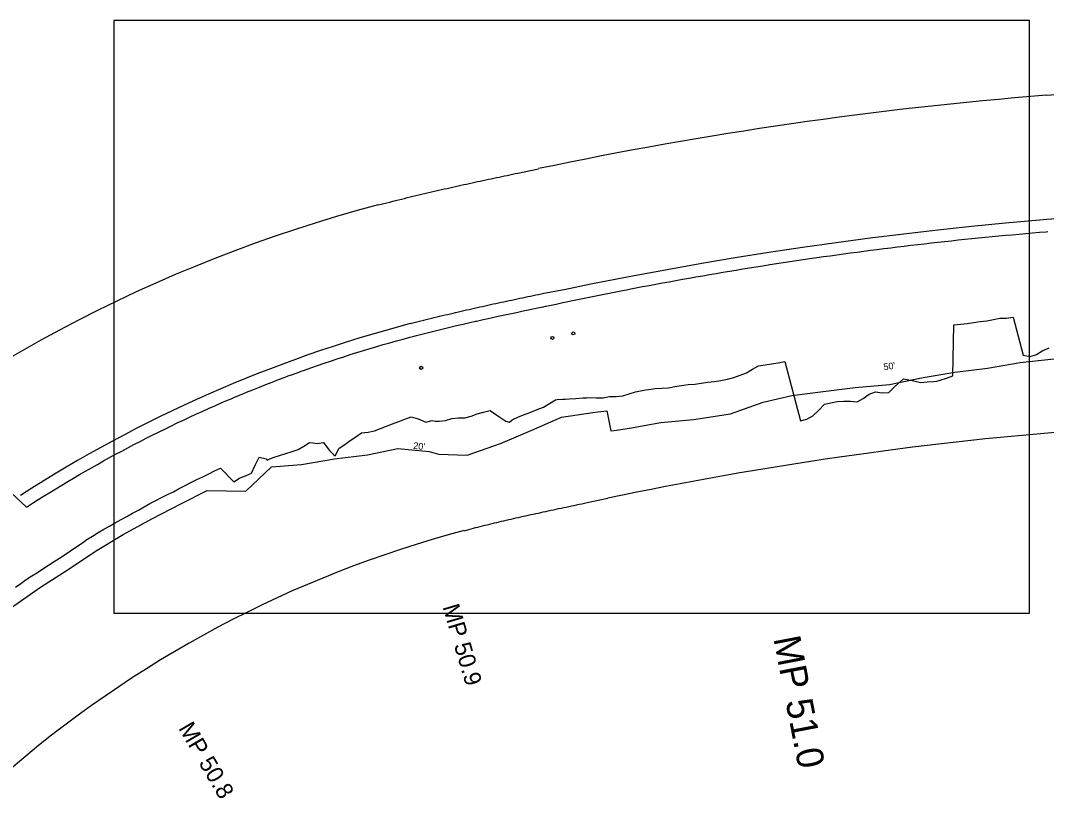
# Model space of a CAD drawing. Extents: x 7860037 to 7875910, y 598622 to 603049.
# Drawn here: x 7868936 to 7870460, y 601894 to 603049 of the extents above; entities that cross this region are included whole.
import ezdxf

# ---------------------------------------------------------------- set-up
doc = ezdxf.new("R2010")
doc.units = 0
for name, color, linetype in [('Level 11', 7, 'Continuous'), ('Level 15', 7, 'Continuous'), ('Level 16', 7, 'Continuous'), ('Level 24', 7, 'Continuous'), ('Level 63', 7, 'Continuous'), ('P_RW_EASE_Perm', 7, 'Continuous')]:
    doc.layers.add(name, color=color, linetype=linetype)

msp = doc.modelspace()

# ---------------------------------------------------------------- linework, layer by layer
at = {"layer": 'Level 11'}
for centre in [(7869757.2, 602584.3), (7869726.2, 602577.8), (7869531.3, 602533.3)]:
    msp.add_circle(centre, 2.25, dxfattribs=at)
at = {"layer": 'Level 16'}
for points in [[(7868915.1, 602354.4), (7868945.4, 602326.6), (7868954.1, 602332.1), (7868962.7, 602337.6), (7868971.4, 602343), (7868980.1, 602348.4), (7868988.8, 602353.8), (7868997.6, 602359.1), (7869006.4, 602364.4), (7869015.2, 602369.6), (7869024, 602374.8), (7869032.9, 602379.9), (7869041.8, 602385), (7869050.7, 602390), (7869059.7, 602395), (7869068.6, 602400), (7869077.6, 602404.9), (7869086.7, 602409.7), (7869095.7, 602414.5), (7869104.8, 602419.3), (7869113.9, 602424), (7869123, 602428.7), (7869132.1, 602433.3), (7869141.3, 602437.9), (7869150.5, 602442.4), (7869159.7, 602446.9), (7869168.9, 602451.4), (7869178.2, 602455.7), (7869187.5, 602460.1), (7869196.8, 602464.4), (7869206.1, 602468.6), (7869215.5, 602472.8), (7869216.6, 602473.3), (7869224.8, 602477), (7869234.2, 602481.1), (7869243.6, 602485.1), (7869249.3, 602487.5), (7869252.3, 602488.8), (7869253.1, 602489.1), (7869261.6, 602492.7), (7869262.5, 602493.1), (7869265.6, 602494.3), (7869272, 602497), (7869281.5, 602500.8), (7869291, 602504.7), (7869300.5, 602508.4), (7869310.1, 602512.1), (7869319.6, 602515.8), (7869329.2, 602519.4), (7869334, 602521.2), (7869338.8, 602523), (7869348.5, 602526.5), (7869351.1, 602527.5), (7869352.9, 602528.1), (7869356.6, 602529.4), (7869358.1, 602530), (7869367.7, 602533.4), (7869377.4, 602536.8), (7869387.1, 602540.1), (7869396.8, 602543.4), (7869406.6, 602546.6), (7869416.3, 602549.8), (7869426.1, 602552.9), (7869435.8, 602556), (7869445.6, 602559), (7869455.4, 602562), (7869465.3, 602564.9), (7869475.1, 602567.8), (7869484.9, 602570.6), (7869494.8, 602573.3), (7869504.7, 602576.1), (7869514.6, 602578.7), (7869518.9, 602579.9), (7869524.5, 602581.3), (7869534.4, 602583.9), (7869544.3, 602586.4), (7869554.2, 602588.9), (7869564.1, 602591.3), (7869574, 602593.6), (7869583.9, 602596), (7869593.8, 602598.3), (7869603.7, 602600.5), (7869612, 602602.4), (7869613.6, 602602.8), (7869623.5, 602605), (7869628.4, 602606), (7869633.4, 602607.1), (7869643.2, 602609.3), (7869653.1, 602611.4), (7869662.9, 602613.5), (7869672.8, 602615.6), (7869682.6, 602617.7), (7869692.4, 602619.8), (7869702.2, 602621.8), (7869704.6, 602622.3), (7869712, 602623.9), (7869713, 602624.1), (7869716.3, 602624.8), (7869721.8, 602626), (7869731.6, 602628), (7869741.4, 602630.1), (7869747.3, 602631.3), (7869751.2, 602632.2), (7869761.1, 602634.2), (7869761.1, 602634.2), (7869770.9, 602636.3), (7869780.8, 602638.3), (7869790.7, 602640.3), (7869800.6, 602642.3), (7869810.5, 602644.3), (7869820.4, 602646.3), (7869830.3, 602648.2), (7869836.2, 602649.3), (7869840.2, 602650.1), (7869850.1, 602652), (7869860, 602653.9), (7869869.9, 602655.7), (7869879.8, 602657.6), (7869889.7, 602659.4), (7869899.6, 602661.2), (7869909.6, 602663), (7869919.5, 602664.8), (7869929.4, 602666.6), (7869939.3, 602668.3), (7869949.3, 602670.1), (7869959.2, 602671.8), (7869969.1, 602673.5), (7869979.1, 602675.2), (7869989, 602676.8), (7869999, 602678.5), (7870008.9, 602680.1), (7870018.9, 602681.8), (7870028.8, 602683.4), (7870038.8, 602684.9), (7870048.8, 602686.5), (7870058.7, 602688.1), (7870068.7, 602689.6), (7870078.7, 602691.1), (7870088.6, 602692.6), (7870098.6, 602694.1), (7870108.6, 602695.5), (7870118.6, 602697), (7870128.5, 602698.4), (7870138.5, 602699.8), (7870148.5, 602701.2), (7870158.5, 602702.5), (7870168.5, 602703.9), (7870178.5, 602705.2), (7870188.5, 602706.6), (7870198.5, 602707.9), (7870208.5, 602709.1), (7870218.5, 602710.4), (7870223.5, 602711), (7870228.5, 602711.6), (7870238.5, 602712.9), (7870248.5, 602714.1), (7870258.5, 602715.3), (7870268.6, 602716.4), (7870273.6, 602717), (7870278.6, 602717.6), (7870288.6, 602718.7), (7870298.6, 602719.8), (7870308.6, 602721), (7870318.7, 602722), (7870328.7, 602723.1), (7870338.7, 602724.1), (7870348.8, 602725.2), (7870358.8, 602726.2), (7870368.8, 602727.2), (7870378.9, 602728.1), (7870388.9, 602729.1), (7870398.9, 602730.1), (7870409, 602731), (7870419, 602731.9), (7870429.1, 602732.8), (7870439.1, 602733.7), (7870449.2, 602734.5), (7870459.2, 602735.4), (7870461.8, 602735.6)], [(7869365.5, 602422.6), (7869371, 602421.7), (7869376.4, 602421.1), (7869386.3, 602422.2), (7869391.6, 602415.2), (7869395.2, 602410.6), (7869401.3, 602404.5), (7869403.6, 602402.6), (7869409.7, 602414), (7869418, 602419.4), (7869426.1, 602425.2), (7869434.4, 602430.7), (7869442.6, 602436.9), (7869452.5, 602437.6), (7869461.9, 602439.7), (7869470.9, 602443.3), (7869479.9, 602446.8), (7869488.9, 602450.3), (7869498, 602453.7), (7869507.1, 602457.1), (7869516.2, 602460.4), (7869527, 602457.4), (7869538.3, 602452.7), (7869547.6, 602455.2), (7869552.2, 602454.3), (7869557.8, 602453.9), (7869567.3, 602455.3), (7869576.6, 602457.9), (7869586.3, 602458.9), (7869596.2, 602458.9), (7869605.5, 602461.7), (7869614.6, 602465.1), (7869624, 602467.7), (7869633.5, 602469.8), (7869643.4, 602463.1), (7869645.3, 602461.8), (7869657, 602454.3), (7869662.3, 602452.6), (7869666.6, 602456), (7869675.6, 602460.4), (7869684.9, 602464), (7869694.2, 602467.7), (7869703.5, 602471.4), (7869712.8, 602475.1), (7869721.9, 602480.1), (7869730.9, 602485.9), (7869733.2, 602486.3), (7869740.9, 602486.7), (7869741.9, 602486.8), (7869745.3, 602487), (7869751, 602487.3), (7869761.1, 602487.9), (7869771.2, 602488.5), (7869777.2, 602488.8), (7869781.2, 602489), (7869791.3, 602488.9), (7869791.3, 602488.9), (7869801.4, 602488.5), (7869811, 602490.5), (7869820.9, 602490.9), (7869830.8, 602491.7), (7869840.2, 602494.8), (7869849.6, 602497.8), (7869859.2, 602499.8), (7869865, 602500.7), (7869868.9, 602501.3), (7869878.7, 602502.6), (7869888.6, 602503.2), (7869898.4, 602503.8), (7869908.1, 602505.7), (7869917.8, 602507), (7869927.5, 602508.3), (7869937.4, 602509), (7869947.1, 602510.5), (7869956.8, 602511.8), (7869966.6, 602512.9), (7869976.3, 602514.5), (7869985.9, 602516.3), (7869995.4, 602518.9), (7870004.8, 602522.3), (7870014.2, 602525.8), (7870023.2, 602531.5), (7870032.3, 602536.4), (7870042, 602537.9), (7870051.7, 602539.4), (7870061.5, 602540.9), (7870071.1, 602542.8), (7870094.6, 602454.6), (7870104, 602457.1), (7870113, 602462.2), (7870121.6, 602470.6), (7870130.1, 602479.1), (7870139.6, 602481.5), (7870149.2, 602483.1), (7870158.8, 602484), (7870168.7, 602483.8), (7870178.6, 602483), (7870187.7, 602487.6), (7870196.6, 602494.3), (7870206, 602497.6), (7870216, 602496.3), (7870225.7, 602496.6), (7870234.4, 602505.5), (7870243.2, 602513.1), (7870247.7, 602516.9), (7870252.7, 602515.9), (7870262.8, 602513.8), (7870272.9, 602511.3), (7870282.5, 602512.5), (7870292.2, 602513.1), (7870297.1, 602513.4), (7870301.8, 602515), (7870311.2, 602518.1), (7870320.7, 602521.2), (7870322.2, 602597.3), (7870332, 602598), (7870341.8, 602599.3), (7870351.6, 602600.6), (7870361.4, 602602), (7870371.2, 602603.2), (7870380.9, 602605), (7870390.6, 602606.8), (7870400.5, 602607.2), (7870410.3, 602608.6), (7870425.4, 602551.9), (7870435.4, 602550.3), (7870444.9, 602553.1), (7870454.2, 602558.8), (7870463.7, 602563.1)], [(7869305.6, 602397.5), (7869311.6, 602400.2), (7869321, 602403.1), (7869330.2, 602406), (7869339.5, 602409), (7869348.8, 602411.8), (7869357.2, 602417), (7869365.5, 602422.6)], [(7869233.4, 602384.4), (7869253.3, 602364.2), (7869261.6, 602369.3), (7869262.7, 602369.9), (7869270.5, 602373.1), (7869279.3, 602377.1), (7869284.9, 602388.7), (7869288.2, 602395.7), (7869290, 602399.5), (7869290.5, 602400.5)], [(7869290.5, 602400.5), (7869300.9, 602398.2), (7869302.8, 602396.2)], [(7868929.1, 602207.5), (7868937, 602213.3), (7868944.9, 602219.1), (7868953.2, 602224.3), (7868961.4, 602229.6), (7868969.6, 602234.9), (7868977.9, 602240.1), (7868986.1, 602245.5), (7868994.3, 602250.8), (7869002.5, 602256.2), (7869010.7, 602261.6), (7869018.7, 602267.2), (7869026.8, 602272.7), (7869034.9, 602278.2), (7869043.2, 602283.4), (7869051.5, 602288.6), (7869060, 602293.6), (7869068.5, 602298.4), (7869077.1, 602303.1), (7869085.6, 602307.9), (7869094.2, 602312.6), (7869102.8, 602317.3), (7869111.4, 602322), (7869119.9, 602326.9), (7869128.4, 602331.7), (7869137.1, 602336.3), (7869145.8, 602340.6), (7869154.6, 602345), (7869163.3, 602349.4), (7869172, 602353.9), (7869180.8, 602358.4), (7869189.5, 602362.8), (7869198.2, 602367.3), (7869207, 602371.6), (7869215.8, 602375.9), (7869224.6, 602380.2), (7869233.4, 602384.4)], [(7869302.8, 602396.2), (7869305.6, 602397.5)]]:
    msp.add_lwpolyline(points, dxfattribs=at)
at = {"layer": 'Level 24'}
msp.add_line((7869807, 602469.3), (7869813.1, 602439.7), dxfattribs=at)
for points in [[(7869947.8, 602688.5), (7869997.7, 602696.9), (7870047.6, 602704.9), (7870097.6, 602712.4), (7870147.7, 602719.6), (7870197.8, 602726.2), (7870248, 602732.4), (7870298.3, 602738.2), (7870348.6, 602743.6), (7870398.9, 602748.5), (7870449.3, 602753), (7870460.3, 602753.9), (7870488.4, 602756.2), (7870499.4, 602757), (7870516.3, 602758.4), (7870549.3, 602761), (7870599.1, 602765), (7870648.9, 602769), (7870698.8, 602773), (7870748.6, 602777), (7870798.5, 602781), (7870847.3, 602784.9)], [(7869713.5, 602644.1), (7869743.5, 602649.4), (7869783.4, 602657.9), (7869845, 602669.8), (7869947.8, 602688.5)], [(7869515.2, 602598.9), (7869519.1, 602599.9), (7869523.1, 602600.9), (7869527, 602602), (7869531, 602603), (7869535, 602604), (7869538.9, 602605), (7869542.9, 602606), (7869546.9, 602607), (7869550.8, 602607.9), (7869554.8, 602608.9), (7869558.7, 602609.9), (7869562.7, 602610.8), (7869566.7, 602611.8), (7869570.6, 602612.7), (7869574.6, 602613.7), (7869578.6, 602614.6), (7869582.5, 602615.5), (7869586.5, 602616.5), (7869590.5, 602617.4), (7869594.5, 602618.3), (7869598.4, 602619.2), (7869602.4, 602620.1), (7869606.4, 602621), (7869610.3, 602621.9), (7869614.3, 602622.8), (7869618.3, 602623.7), (7869622.2, 602624.6), (7869626.2, 602625.4), (7869630.2, 602626.3), (7869634.2, 602627.2), (7869638.1, 602628.1), (7869642.1, 602628.9), (7869646.1, 602629.8), (7869650, 602630.6), (7869654, 602631.5), (7869658, 602632.3), (7869661.9, 602633.2), (7869665.9, 602634), (7869669.9, 602634.9), (7869673.8, 602635.7), (7869677.8, 602636.6), (7869681.8, 602637.4), (7869685.7, 602638.3), (7869689.7, 602639.1), (7869693.7, 602639.9), (7869697.6, 602640.8), (7869701.6, 602641.6), (7869705.6, 602642.4), (7869709.5, 602643.3), (7869713.5, 602644.1)], [(7869813.1, 602439.7), (7869818.1, 602440.1), (7869840.6, 602443.5), (7869887.3, 602452.3), (7869935.6, 602456.6), (7869990.4, 602464.9), (7870039.1, 602482.5), (7870081.8, 602492.3), (7870128, 602498.3), (7870175.7, 602504.2), (7870226.5, 602508.6), (7870276.9, 602518.7), (7870323.7, 602526.7), (7870372.4, 602533), (7870420.5, 602541.2), (7870466.2, 602546.2), (7870477.2, 602546.6), (7870508.4, 602550.4), (7870520.3, 602552.5), (7870534.9, 602554.9), (7870566.4, 602557.8), (7870617.2, 602563), (7870630.2, 602564.8)], [(7869309.1, 602386.5), (7869353.7, 602390), (7869402.5, 602398.4), (7869451.8, 602404), (7869496.7, 602413.5), (7869543, 602408.9), (7869557, 602405.3), (7869599.6, 602403.6), (7869649.3, 602420.9), (7869695.6, 602440.7), (7869739.6, 602459.8), (7869786.2, 602467.1), (7869793.7, 602468.1), (7869807, 602469.3)], [(7869213.6, 602351.2), (7869270.8, 602350.2), (7869309.1, 602386.5)], [(7868796, 602036.2), (7868803.9, 602045.8), (7868831.7, 602076.6), (7868853.8, 602124.3), (7868887.1, 602152.5), (7868926.5, 602180), (7868966.2, 602207.8), (7869007.2, 602234.1), (7869047.5, 602261.3), (7869088.9, 602285.7), (7869131.2, 602309.1), (7869174.4, 602331.4), (7869213.6, 602351.2)]]:
    msp.add_lwpolyline(points, dxfattribs=at)
msp.add_arc((7870030.6, 600645.1), 2020.7, 104.7794, 122.7884, dxfattribs=at)
at = {"layer": 'Level 63'}
msp.add_lwpolyline([(7869074.7, 602169), (7870434.7, 602169), (7870434.7, 603049), (7869074.7, 603049)], close=True, dxfattribs=at)
at = {"layer": 'P_RW_EASE_Perm'}
for p, q in [((7870459.8, 602938), (7871182.6, 602995.8)), ((7869674.8, 602822.4), (7869705.7, 602829)), ((7869777.7, 602333.2), (7869808.6, 602339.7))]:
    msp.add_line(p, q, dxfattribs=at)
for points in [[(7869467.6, 602775.1), (7869471.7, 602776.1), (7869476.1, 602777.3), (7869480.4, 602778.4), (7869484.7, 602779.5), (7869489.1, 602780.6), (7869493.4, 602781.7), (7869497.7, 602782.8), (7869502, 602783.9), (7869506.3, 602784.9), (7869510.6, 602786), (7869514.9, 602787), (7869519.1, 602788.1), (7869523.4, 602789.1), (7869527.6, 602790.1), (7869531.9, 602791.1), (7869536.1, 602792.1), (7869540.4, 602793.1), (7869544.6, 602794.1), (7869548.8, 602795.1), (7869553, 602796), (7869557.2, 602797), (7869561.4, 602797.9), (7869565.5, 602798.9), (7869569.7, 602799.8), (7869573.9, 602800.8), (7869578, 602801.7), (7869582.2, 602802.6), (7869586.3, 602803.5), (7869590.4, 602804.4), (7869594.5, 602805.3), (7869598.6, 602806.2), (7869602.7, 602807.1), (7869606.8, 602808), (7869610.9, 602808.9), (7869614.9, 602809.8), (7869619, 602810.6), (7869623, 602811.5), (7869627.1, 602812.4), (7869631.1, 602813.2), (7869635.1, 602814.1), (7869639.1, 602814.9), (7869643.1, 602815.8), (7869647.1, 602816.6), (7869651.1, 602817.5), (7869655.1, 602818.3), (7869659, 602819.1), (7869663, 602820), (7869666.9, 602820.8), (7869670.8, 602821.6), (7869674.8, 602822.4)], [(7869594.9, 602291.5), (7869598.6, 602292.5), (7869602, 602293.4), (7869605.4, 602294.3), (7869608.8, 602295.1), (7869612.2, 602296), (7869615.6, 602296.9), (7869619.1, 602297.8), (7869622.5, 602298.6), (7869626, 602299.5), (7869629.5, 602300.3), (7869633, 602301.2), (7869636.5, 602302), (7869640, 602302.9), (7869643.5, 602303.7), (7869647.1, 602304.6), (7869650.6, 602305.4), (7869654.2, 602306.2), (7869657.7, 602307.1), (7869661.3, 602307.9), (7869664.9, 602308.7), (7869668.5, 602309.5), (7869672.1, 602310.4), (7869675.8, 602311.2), (7869679.4, 602312), (7869683.1, 602312.8), (7869686.7, 602313.6), (7869690.4, 602314.5), (7869694.1, 602315.3), (7869697.8, 602316.1), (7869701.5, 602316.9), (7869705.2, 602317.7), (7869708.9, 602318.5), (7869712.6, 602319.3), (7869716.4, 602320.1), (7869720.1, 602321), (7869723.9, 602321.8), (7869727.7, 602322.6), (7869731.5, 602323.4), (7869735.3, 602324.2), (7869739.1, 602325), (7869742.9, 602325.8), (7869746.7, 602326.6), (7869750.5, 602327.4), (7869754.4, 602328.2), (7869758.3, 602329.1), (7869762.1, 602329.9), (7869766, 602330.7), (7869769.9, 602331.5), (7869773.8, 602332.3), (7869777.7, 602333.2)]]:
    msp.add_lwpolyline(points, dxfattribs=at)
for centre, radius, start, end in [((7870936.7, 596977.5), 5979.6, 94.57443, 101.88023), ((7870030.6, 600645.1), 2203.2, 104.8137, 131.2967), ((7870936.7, 596977.5), 5479.6, 94.5744, 101.8802), ((7870030.6, 600645.1), 1703.2, 104.8137, 131.2967)]:
    msp.add_arc(centre, radius, start, end, dxfattribs=at)

# ---------------------------------------------------------------- texts
at = {"layer": 'Level 15'}
for s, height, rotation, p in [('MP 50.9', 25, 286.4979, (7869562.9, 602178.5)), ('MP 51.0', 40, 280.9232, (7870054.2, 602131.6)), ('MP 50.8', 25, 300.3886, (7869170.2, 601998.2))]:
    msp.add_text(s, height=height, rotation=rotation, dxfattribs=at).set_placement(p)
at = {"layer": 'Level 24'}
for s, rotation, p in [("50'", 8.4528, (7870218.5, 602529.5)), ("20'", 353.5065, (7869519.1, 602413.1))]:
    msp.add_text(s, height=10, rotation=rotation, dxfattribs=at).set_placement(p)

doc.saveas('drawing.dxf')
